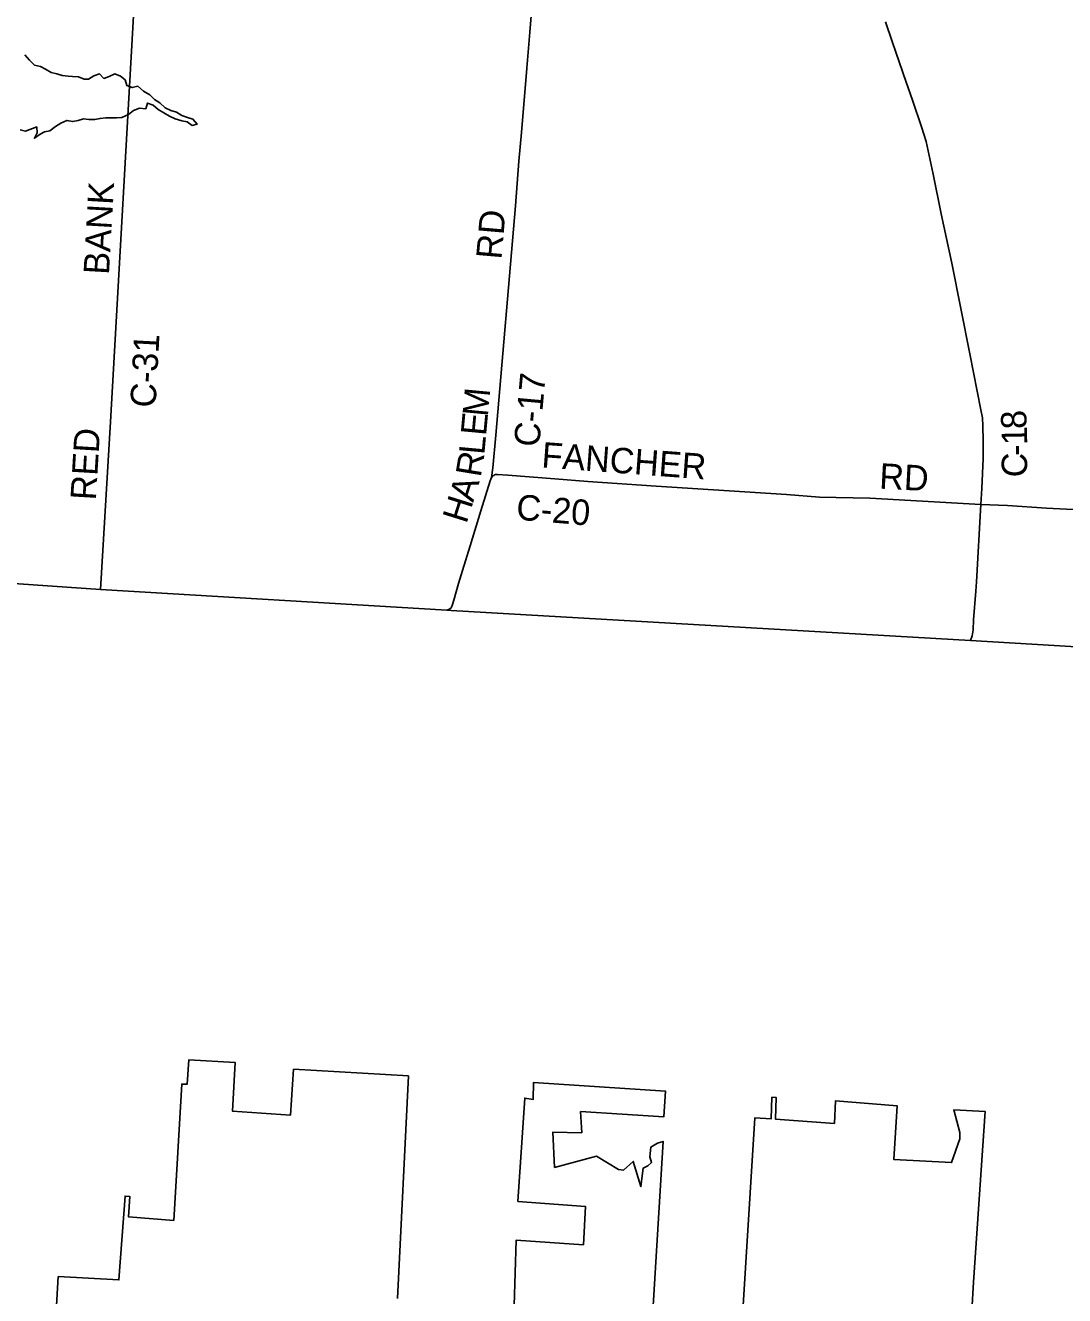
# Model space of a CAD drawing. Extents: x 1674899 to 2057726, y 653888 to 988278.
# Drawn here: x 1867438 to 1879677, y 767682 to 782644 of the extents above; entities that cross this region are included whole.
import ezdxf

# ---------------------------------------------------------------- set-up
doc = ezdxf.new("R2010")
doc.units = 0
for name, color, linetype in [('GM_X_Adjacent_County', 7, 'Continuous'), ('GM_X_Corporation', 7, 'Continuous'), ('GM_X_County', 7, 'Continuous'), ('GM_X_County_Road', 7, 'Continuous'), ('GM_X_County_Road_Text', 7, 'Continuous'), ('GM_X_Major_Lake', 7, 'Continuous'), ('GM_X_Township', 7, 'Continuous')]:
    doc.layers.add(name, color=color, linetype=linetype)

msp = doc.modelspace()

# ---------------------------------------------------------------- linework, layer by layer
at = {"layer": 'GM_X_Adjacent_County'}
msp.add_lwpolyline([(1854746, 776908), (1855849, 776844), (1860837, 776510), (1864331, 776270), (1865938, 776163), (1868321, 776001), (1872401, 775756), (1872453, 775754), (1878568, 775400), (1881788, 775208), (1885545, 774992), (1886187, 774949), (1887084, 774902), (1887135, 774898), (1889887, 774731), (1895282, 774451), (1895251, 773958), (1895161, 772565), (1894704, 764108)], dxfattribs=at)
at = {"layer": 'GM_X_Corporation'}
for points in [[(1867681, 765439), (1867825, 767906), (1868539, 767866), (1868613, 768854), (1868670, 768848), (1868654, 768608), (1869185, 768567), (1869280, 770173), (1869342, 770172), (1869364, 770460), (1869908, 770428), (1869876, 769856), (1870561, 769808), (1870596, 770349), (1871949, 770269), (1871820, 767647)], [(1873193, 767564), (1873219, 768336), (1874011, 768281), (1874036, 768730), (1873238, 768791), (1873320, 770008), (1873417, 769992), (1873424, 770194), (1874979, 770090), (1874958, 769789), (1873978, 769850), (1873991, 769601), (1873651, 769608), (1873671, 769192), (1874165, 769326), (1874423, 769168), (1874483, 769161), (1874597, 769263), (1874687, 768966), (1874715, 769184), (1874768, 769209), (1874814, 769250), (1874791, 769315), (1874805, 769431), (1874883, 769476), (1874949, 769499), (1874823, 767432)], [(1875756, 765359), (1876031, 769777), (1876220, 769763), (1876230, 770019), (1876282, 770015), (1876273, 769759), (1876966, 769711), (1876978, 769975), (1877705, 769919), (1877667, 769284), (1878347, 769249), (1878442, 769529), (1878442, 769603), (1878372, 769872), (1878741, 769851), (1878604, 767840), (1878567, 767165)]]:
    msp.add_lwpolyline(points, dxfattribs=at)
at = {"layer": 'GM_X_County'}
msp.add_lwpolyline([(1881788, 775208), (1878568, 775400), (1872453, 775754), (1872401, 775756), (1868321, 776001), (1865938, 776163), (1864331, 776270), (1860837, 776510), (1855849, 776844), (1854746, 776908)], dxfattribs=at)
at = {"layer": 'GM_X_County_Road'}
for points in [[(1868321, 776001), (1868439, 777975), (1868734, 783178)], [(1872927, 777320), (1872945, 777432), (1872978, 777819), (1873212, 780520), (1873251, 781046), (1873282, 781384), (1873344, 782141), (1873381, 782566), (1873402, 782850)], [(1878568, 775400), (1878590, 775455), (1878599, 775524), (1878604, 775641), (1878633, 775979), (1878640, 776088), (1878691, 776999), (1878702, 777191), (1878720, 777542), (1878720, 777749), (1878716, 777928), (1878712, 778020), (1878692, 778117), (1878562, 778774), (1878349, 779845), (1878222, 780426), (1878129, 780890), (1878049, 781278), (1877993, 781449), (1877886, 781763), (1877812, 781976), (1877647, 782454), (1877568, 782686)], [(1872401, 775756), (1872432, 775766), (1872438, 775770), (1872452, 775785), (1872457, 775793), (1872468, 775823), (1872484, 775872), (1872540, 776071), (1872587, 776224), (1872678, 776514), (1872803, 776927), (1872912, 777278), (1872927, 777320)], [(1872927, 777320), (1872944, 777337), (1872954, 777344), (1872965, 777349), (1872976, 777353), (1872988, 777355), (1873000, 777356), (1873120, 777346), (1873673, 777303), (1874061, 777272), (1874867, 777216), (1876402, 777119), (1876790, 777089), (1877384, 777075), (1878691, 776999)], [(1878691, 776999), (1879006, 776989), (1879466, 776957), (1880249, 776920)], [(1864331, 776270), (1865938, 776163), (1868321, 776001)], [(1868321, 776001), (1872401, 775756)]]:
    msp.add_lwpolyline(points, dxfattribs=at)
at = {"layer": 'GM_X_Major_Lake'}
msp.add_lwpolyline([(1867431, 782296), (1867487, 782233), (1867546, 782175), (1867616, 782160), (1867676, 782128), (1867742, 782091), (1867808, 782073), (1867872, 782054), (1867943, 782046), (1867995, 782044), (1868063, 782037), (1868129, 782009), (1868181, 782009), (1868244, 782052), (1868310, 782072), (1868361, 782019), (1868426, 782041), (1868490, 782073), (1868560, 782046), (1868615, 782002), (1868631, 781936), (1868697, 781911), (1868763, 781927), (1868831, 781868), (1868902, 781826), (1868958, 781773), (1869022, 781731), (1869083, 781672), (1869151, 781640), (1869217, 781622), (1869281, 781583), (1869347, 781561), (1869411, 781540), (1869460, 781480), (1869404, 781466), (1869344, 781507), (1869279, 781519), (1869201, 781545), (1869135, 781574), (1869069, 781614), (1869001, 781653), (1868944, 781705), (1868876, 781730), (1868855, 781662), (1868781, 781668), (1868713, 781641), (1868651, 781595), (1868575, 781561), (1868511, 781554), (1868451, 781556), (1868387, 781556), (1868317, 781549), (1868255, 781535), (1868185, 781537), (1868121, 781542), (1868060, 781522), (1867996, 781512), (1867928, 781525), (1867856, 781493), (1867792, 781453), (1867728, 781402), (1867664, 781390), (1867611, 781362), (1867545, 781315), (1867576, 781377), (1867572, 781449), (1867440, 781397), (1867376, 781414)], dxfattribs=at)
at = {"layer": 'GM_X_Township'}
for points in [[(1881788, 775208), (1878568, 775400), (1872453, 775754), (1872401, 775756), (1868321, 776001), (1868439, 777975), (1868734, 783178), (1868751, 783613), (1868806, 784389), (1868890, 785515), (1868892, 785569), (1868914, 786029), (1869008, 787459), (1869000, 787580), (1869039, 787768), (1869111, 789007), (1869163, 789806), (1869596, 797271), (1870008, 803514), (1877369, 802994), (1883392, 802588)], [(1868734, 783178), (1868439, 777975), (1868321, 776001), (1865938, 776163), (1864331, 776270), (1860837, 776510), (1855849, 776844), (1854746, 776908)]]:
    msp.add_lwpolyline(points, dxfattribs=at)

# ---------------------------------------------------------------- texts
at = {"layer": 'GM_X_County_Road_Text'}
for s, rotation, p in [('BANK', 86.7295, (1868422, 779703)), ('RD', 85.0719, (1873045, 779882)), ('C-31', 86.9143, (1868971, 778137)), ('C-17', 84.837, (1873489, 777671)), ('M', 84.7101, (1872884, 778028)), ('E', 84.7041, (1872863, 777804)), ('8', 92.8143, (1879234, 777896)), ('RED', 86.5725, (1868268, 777046)), ('1', 91.1376, (1879238, 777702)), ('L', 84.8255, (1872843, 777581)), ('FANCHER', 355.7921, (1873511, 777438)), ('R', 80.6514, (1872800, 777314)), ('C', 88.3722, (1879232, 777317)), ('-', 90.5687, (1879239, 777576)), ('RD', 357.0388, (1877490, 777188)), ('A', 72.7672, (1872711, 777018)), ('H', 72.5794, (1872632, 776765)), ('C-20', 355.2094, (1873211, 776824))]:
    msp.add_text(s, height=300, rotation=rotation, dxfattribs=at).set_placement(p)

doc.saveas('drawing.dxf')
